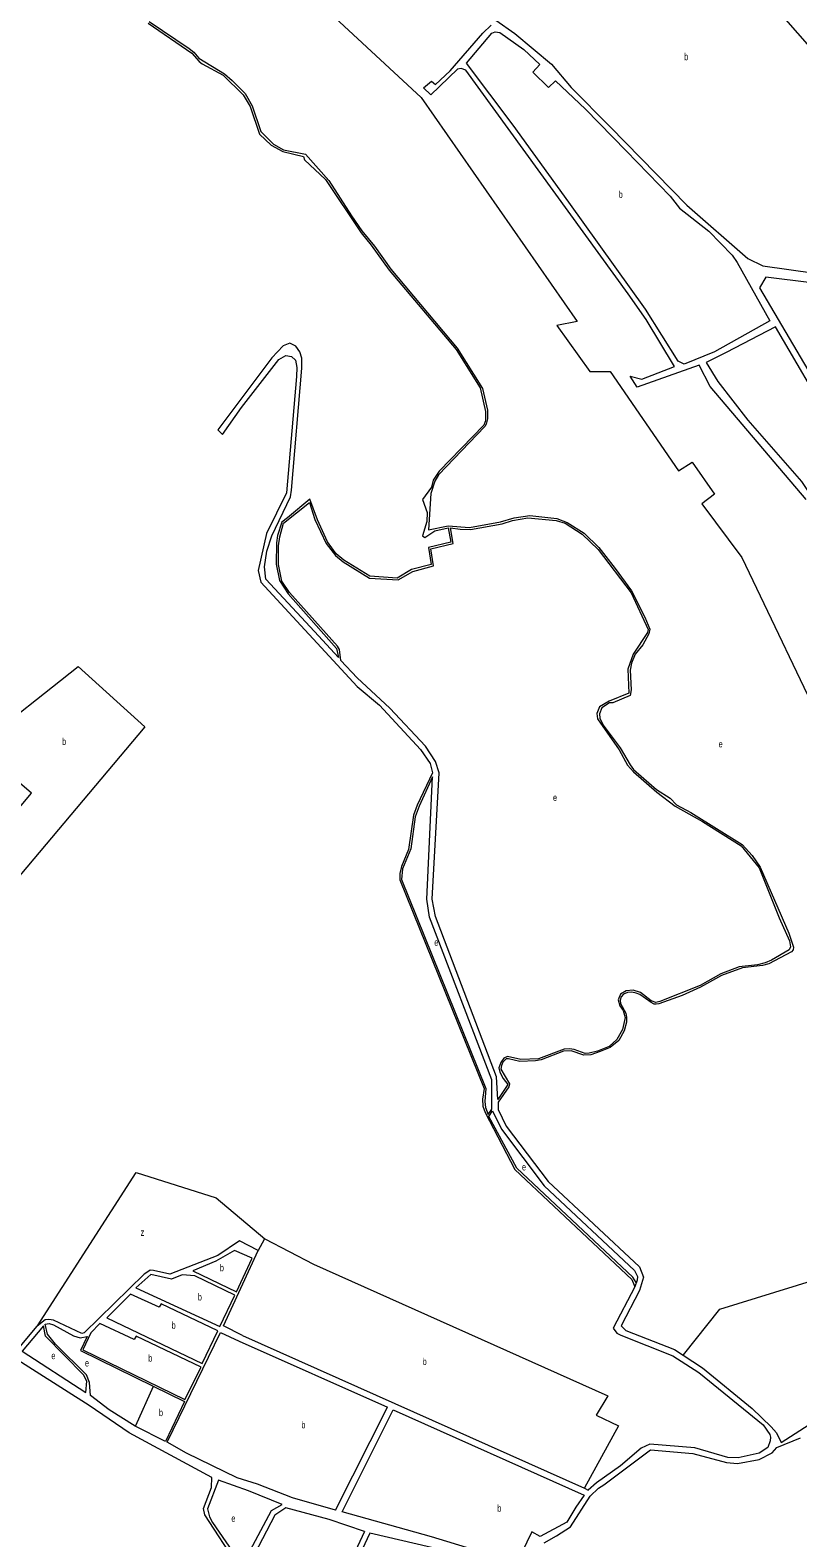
# Model space of a CAD drawing. Extents: x 639657 to 671642, y 222838 to 252123.
# Drawn here: x 646186 to 647287, y 244084 to 246247 of the extents above; entities that cross this region are included whole.
import ezdxf

# ---------------------------------------------------------------- set-up
doc = ezdxf.new("R2010")
doc.units = 0
doc.header["$LTSCALE"] = 4
doc.layers.add('1', color=7, linetype='Continuous', lineweight=13)
doc.layers.add('21', color=7, linetype='Continuous', lineweight=13)
doc.layers.add('7', color=7, linetype='Continuous')

msp = doc.modelspace()

# ---------------------------------------------------------------- linework, layer by layer
at = {"layer": '1'}
for p, q in [((647056.52, 244453.45), (647053.29, 244444.21)), ((646485.99, 244366.3), (646698.397, 244271.227)), ((646624.175, 244123.776), (646698.397, 244271.227)), ((646633.337, 244121.211), (646706.927, 244267.409)), ((646706.927, 244267.409), (646980.546, 244144.938)), ((646665.762, 244092.884), (646601.79, 243957.656)), ((646673.246, 244090.439), (646610.085, 243956.922))]:
    msp.add_line(p, q, dxfattribs=at)
for points in [[(647349.01, 246172.29), (647246.15, 246289.66)], [(646355.16, 246257.03), (646418.04, 246214.05), (646428.18, 246202.06), (646432.49, 246198.85), (646463.06, 246182.62), (646491.66, 246154.41), (646501.76, 246137.45), (646514.88, 246097.98), (646531.69, 246082.14), (646548.48, 246072.96), (646578.16, 246065.95), (646579.47, 246061.02), (646609.85, 246032.77), (646660.98, 245956.03), (646675.36, 245938.4), (646700.88, 245902.51), (646797.22, 245788.77), (646831.53, 245733.96), (646839, 245700.02), (646838.98, 245686.71), (646836.61, 245680.48), (646772.49, 245614.42), (646764.1, 245601.33), (646761.72, 245591.24), (646748.59, 245573.43), (646755.66, 245554.95), (646755.21, 245542.06), (646748.95, 245521.66), (646751.96, 245519.29), (646766.37, 245528.51), (646785.71, 245532.99), (646789.34, 245512.58), (646757.53, 245504.89), (646761.15, 245480.61), (646733.2, 245473.35), (646712.35, 245460.92), (646673.24, 245463.55), (646635.88, 245486.38), (646625.15, 245495.85), (646612.5, 245513.05), (646598.14, 245544.44), (646587.22, 245574.32), (646555.17, 245547.3), (646546.78, 245541.29), (646540.74, 245521.75), (646539.23, 245511.66), (646538.76, 245480.94), (646543.45, 245457.3), (646555.89, 245438.37), (646625.41, 245359.63), (646628.09, 245347.16), (646593.85, 245384.38)], [(646356.66, 246259.4), (646414.16, 246220.91), (646420.83, 246215.35), (646427.74, 246206.99), (646464.55, 246184.55), (646475.76, 246174.71), (646494.3, 246156.3), (646504.67, 246138.3), (646516.81, 246101.63), (646534.91, 246083.44), (646549.34, 246075.32), (646580.95, 246068.96), (646614.37, 246031.28), (646646.86, 245980.85), (646661.85, 245959.24), (646679.87, 245937.32), (646703.25, 245904), (646798.51, 245790.71), (646834.75, 245733.1), (646841.8, 245701.95), (646842.21, 245689.49), (646840.27, 245681.55), (646838.33, 245678.33), (646771.84, 245608.84), (646766.46, 245600.04), (646760.63, 245582.22), (646757.56, 245530.24), (646785.71, 245535.79), (646816.01, 245533.59), (646860.5, 245541.69), (646880.49, 245547.46), (646902.84, 245550.65), (646941.29, 245546.3), (646956.11, 245540.7), (646980.59, 245525.41), (647001.62, 245504.97), (647025.21, 245474.86), (647048.81, 245442.61), (647067.88, 245404.98), (647074.73, 245387.78), (647073.43, 245380.91), (647064.6, 245365.24), (647053.84, 245351.71), (647048.67, 245338.83), (647046.72, 245328.95), (647048.19, 245300.58), (647046.67, 245292.42), (647021.73, 245281.71), (647017.01, 245282.14), (647005.82, 245274.64), (647002.59, 245266.26), (647003.01, 245259.81), (647007.72, 245249.71), (647032.39, 245217.22), (647046.54, 245192.92), (647051.68, 245186.03), (647084.3, 245157.62), (647104.05, 245145.13), (647113.28, 245135.66), (647133.46, 245124.45), (647207.53, 245078.57), (647221.47, 245062.65), (647233.05, 245046.08), (647274.17, 244951.65), (647280.81, 244931.22), (647280.59, 244927.56), (647278, 244924.77)], [(647299.09, 245573.73), (647161.57, 245735.85), (647145.71, 245766.37), (647056.71, 245734.93), (647046.85, 245750.4), (647063.17, 245746.51), (647110.04, 245764.27), (647069.73, 245831.96), (647043.78, 245868.72), (646810.79, 246189.49), (646804.34, 246191.83), (646799.18, 246190.96), (646760.81, 246154.17), (646750.25, 246164.23), (646761.62, 246173.7), (646767.22, 246168.99), (646788.23, 246188.58), (646835.35, 246242.77), (646847.35, 246254.39)], [(646854.21, 246261.49), (646881.35, 246242.45), (646933.92, 246198.15), (646961.95, 246164.74), (647017.78, 246108.44), (647127.97, 245995.88), (647215.53, 245919.35), (647237, 245908.8), (647311.34, 245898.39)], [(646593.85, 245384.38), (646523.9, 245459.26), (646521.99, 245476.88), (646525.24, 245499.65), (646532.79, 245521.34), (646559.29, 245577.58), (646560.81, 245586.81), (646575.65, 245762.27), (646575.88, 245776.65), (646572.67, 245785.46), (646566.88, 245793.63), (646558.29, 245797.94), (646548.83, 245794.3), (646532.69, 245776.72), (646455.4, 245673.73), (646461.792, 245666.775), (646489.1, 245705.77), (646542.48, 245774.4), (646552.81, 245780.39), (646560.75, 245778.88), (646566.76, 245773.71), (646568.47, 245763.19), (646568.02, 245750.09), (646553.82, 245583.01), (646524.94, 245524.63), (646512.84, 245471.8), (646516.68, 245455.04), (646655.27, 245305.48), (646687.25, 245278.78), (646746.03, 245215.07), (646759.97, 245194.63), (646763.04, 245181.45), (646741.2, 245134.91), (646735.8, 245120.52), (646728.65, 245071.31), (646718.51, 245047.26), (646716.14, 245036.94), (646716.13, 245028.13), (646837.32, 244728.44), (646834.94, 244713.39), (646835.35, 244703.28), (646838.56, 244694.03), (646881.21, 244612.45), (647049, 244454.32), (647052.441, 244446.21), (647053.29, 244444.21)], [(646655, 245317.9), (646631.4, 245342.64), (646629.92, 245358.33), (646626.7, 245363.06), (646557.83, 245440.09), (646547.11, 245456.43), (646541.98, 245480.5), (646542.01, 245507.36), (646543.96, 245520.03), (646549.15, 245539.57), (646586.57, 245569.16), (646594.49, 245545.09), (646610.78, 245510.69), (646624.08, 245493.06), (646634.81, 245484.02), (646672.81, 245460.76), (646714.06, 245458.55), (646735.13, 245470.12), (646764.37, 245478.24), (646760.75, 245502.95), (646792.77, 245510.43), (646788.93, 245533.2), (646802.9, 245531.25), (646817.72, 245530.8), (646862.86, 245538.9), (646877.69, 245543.6), (646900.04, 245547.22), (646940.43, 245543.51), (646953.32, 245539.84), (646978.01, 245523.91), (647000.75, 245501.75), (647047.94, 245439.81), (647072.37, 245387.36), (647071.5, 245382.84), (647051.05, 245351.72), (647043.5, 245330.03), (647044.53, 245295.64), (647016.58, 245284.51), (647002.6, 245276.15), (646998.94, 245266.48), (646999.79, 245258.96), (647030.88, 245214.43), (647042.88, 245192.49), (647051.25, 245182.81), (647084.73, 245153.96), (647111.13, 245133.51), (647150.42, 245111.53), (647205.81, 245076.64), (647231.54, 245045.01), (647260.24, 244973.6), (647275.23, 244940.47), (647276.51, 244931.65), (647274.57, 244927.36), (647249.2, 244912.77), (647240.17, 244908.91), (647229.2, 244906.13), (647203.2, 244902.94), (647176.55, 244893.3), (647147.3, 244876.56), (647089.26, 244853.41), (647083.67, 244852.13), (647076.8, 244854.29), (647061.56, 244866.35), (647050.82, 244869.59), (647040.72, 244868.74), (647032.77, 244863.81), (647029.53, 244855.86), (647031.67, 244847.04), (647036.39, 244840.58), (647039.6, 244830.26), (647035.49, 244813.06), (647027.52, 244799.09), (647016.33, 244789), (646999.78, 244782.35), (646987.96, 244779.14), (646981.94, 244778.72), (646966.27, 244784.76), (646959.82, 244785.63), (646951.87, 244784.78), (646915.11, 244771.28), (646889.76, 244770.02), (646870.64, 244774.35), (646865.48, 244771.99), (646860.96, 244765.98), (646858.16, 244758.45), (646859.87, 244752), (646864.58, 244742.74), (646871.02, 244734.35), (646856.66, 244712.96), (646854.92, 244745.55), (646767.35, 244975.54), (646762.66, 245000.06), (646772.78, 245181.26), (646767.22, 245197.6), (646752.85, 245219.76)], [(646752.85, 245219.76), (646701.79, 245274.21), (646655, 245317.9)], [(647278, 244924.77), (647245.75, 244907.61), (647236.51, 244904.83)], [(647177.62, 244890.5), (647147.51, 244873.77), (647121.29, 244862.19), (647087.97, 244850.19), (647083.88, 244849.34), (647081.09, 244849.77), (647076.8, 244852.14), (647060.48, 244863.56), (647055.11, 244865.5), (647049.1, 244866.8), (647042.87, 244866.38), (647037.28, 244863.8), (647033.62, 244859.94), (647032.32, 244855.21), (647032.75, 244850.69), (647040.68, 244836.71), (647041.53, 244831.11), (647041.52, 244823.8), (647037.85, 244811.12), (647030.31, 244797.37), (647017.84, 244787.49), (647003.86, 244781.49), (646990.32, 244776.77), (646980.22, 244776.36), (646961.97, 244782.83), (646951.01, 244781.99), (646918.98, 244769.55), (646911.03, 244768.06), (646888.25, 244767.23), (646872.36, 244771.34), (646868.7, 244770.91), (646864.18, 244766.4), (646862.24, 244761.67), (646861.38, 244756.51), (646873.38, 244735.2), (646872.52, 244731.12), (646857.45, 244708.77), (646857.43, 244698.45), (646869, 244674.77), (646928.84, 244595.32), (647060.15, 244472.53), (647065.94, 244457.89), (647060.11, 244438.96), (647033.82, 244388.21), (647040.48, 244381.32), (647110.48, 244353.9), (647122.806, 244345.847)], [(647236.51, 244904.83), (647207.71, 244901.64), (647177.62, 244890.5)], [(646513.01, 244495.99), (646486.18, 244510.01), (646455, 244489.19), (646386.21, 244462.19), (646363.01, 244467.38), (646358.28, 244467.82), (646354.63, 244465.67), (646349.47, 244462.24), (646263.63, 244377.81), (646259.98, 244376.95), (646219.4, 244396.16), (646212.95, 244397.03), (646207.37, 244396.61), (646196.115, 244387.661)], [(646490.51, 244374.25), (646463.24, 244387.85), (646513.01, 244495.99)], [(647053.29, 244444.21), (647022.48, 244384.66), (647027.63, 244377.77), (647033.21, 244374.53), (647107.72, 244344.95), (647145.29, 244321.23), (647237.56, 244245.79), (647247, 244232.22), (647247.85, 244228.13), (647247.42, 244222.97), (647244.18, 244213.29), (647231.49, 244205.35), (647201.41, 244198.5), (647186.59, 244199.39), (647139.55, 244213.01), (647075.11, 244218.27), (647062.64, 244212.69), (647032.74, 244187.13), (646998.55, 244162.86), (646986.443, 244152.495)], [(646196.115, 244387.661), (646195.75, 244387.37), (646168.85, 244355.57), (646150.85, 244366.208)], [(646210.92, 244376.18), (646207.71, 244390.6), (646213.3, 244391.46), (646219.31, 244389.51), (646248.08, 244373.76), (646257.75, 244370.95), (646267.63, 244372.88), (646258.15, 244352.45), (646362.444, 244301.398)], [(646336.65, 244243.89), (646299.51, 244267.61), (646272.68, 244288.09), (646271.2, 244306.81), (646266.7, 244317.58), (646222.5, 244361.75), (646210.92, 244376.18)], [(646624.175, 244123.776), (646562.32, 244141.09), (646512.15, 244160.96), (646482.94, 244169.83), (646410.37, 244205.23), (646382.67, 244220.98), (646458.93, 244378.6), (646485.99, 244366.3)], [(646490.51, 244374.25), (646980.937, 244154.957), (646986.443, 244152.495)], [(646484.06, 244044.13), (646436.46, 244116.73), (646434.54, 244126.2), (646446.18, 244155.89), (646446.63, 244170.31), (646327.9, 244234.61), (646270.8, 244273.65), (646154.02, 244347.84)], [(647122.806, 244345.847), (647150.4, 244327.82), (647221.65, 244269.41), (647249.11, 244243.34), (647256.62, 244234.5), (647263.04, 244220.72), (647341.97, 244271.2), (647409.25, 244297.6), (647462.33, 244306.36), (647592.78, 244332.25), (647604.902, 244336.683)], [(646362.444, 244301.398), (646407.16, 244279.51), (646380.23, 244222.09), (646336.65, 244243.89)], [(646923.38, 244076.91), (646941.23, 244086.57), (646961.23, 244099.68), (646989.43, 244143.78), (647001.05, 244154.95), (647009.01, 244160.11), (647076.01, 244210.21), (647136.69, 244204.94), (647185.01, 244191.97), (647200.7, 244190.45), (647231.86, 244196.44), (647250.35, 244205.88), (647257.02, 244213.62), (647290.77, 244227.14)], [(646980.546, 244144.938), (646968.64, 244128.04), (646955.72, 244106.32), (646917.67, 244085.93), (646905.65, 244092.4), (646884.11, 244047.88), (646761.7, 244085.28), (646633.337, 244121.211)], [(646665.762, 244092.884), (646614.91, 244110.07), (646552.87, 244127.14), (646536.91, 244116.41), (646496.02, 244037.64), (646561.117, 243966.133)], [(646919.543, 244021.867), (646900.74, 244026.39), (646761.59, 244070.06), (646673.246, 244090.439)]]:
    msp.add_lwpolyline(points, dxfattribs=at)
for points in [[(646958.64, 246000.44), (646878.93, 246110.89), (646811.83, 246199.79), (646848.46, 246242.8), (646852.97, 246244.75), (646859.85, 246243.9), (646894.31, 246219.3), (646917.15, 246197.68), (646907.08, 246186.93), (646929.29, 246164.66), (646939.57, 246174.13), (646982.46, 246133.67), (647041.09, 246073.73), (647104.23, 246008.75), (647117.21, 245991.84), (647159.5, 245958.5), (647192.97, 245924.11), (647200.27, 245913.79), (647247.21, 245829.78), (647167.65, 245785.45), (647124.01, 245767.9), (647115.64, 245771.99), (647068.89, 245846.78)], [(647306.59, 245884.44), (647241.06, 245892.48), (647232.23, 245877.25), (647343.93, 245687.28), (647351.44, 245676.96), (647387.06, 245644.05), (647484.09, 245734.98), (647452.58, 245792.99), (647377.02, 245852.36), (647351.69, 245868.28), (647320.98, 245880.77)], [(647336.83, 245681.71), (647254.94, 245821.39), (647184.41, 245784.35), (647155.6, 245770.22), (647172.32, 245743.14), (647215.44, 245687.46), (647292.24, 245599.3), (647421.97, 245403.21), (647466.48, 245427.65), (647502.39, 245445.22), (647494.05, 245473.15), (647415.8, 245601.71), (647393.48, 245625.58)], [(646842.86, 244691.23), (646848.02, 244698.96), (646848.08, 244740.89), (646758.81, 244974.53), (646754.98, 245000.12), (646762.93, 245175.54), (646743.99, 245133.84), (646738.38, 245118.15), (646731.87, 245072.6), (646720.23, 245043.81), (646718.49, 245028.55), (646839.69, 244728.43), (646838.16, 244710.16), (646839, 244701.34)], [(647056.52, 244453.45), (647055.31, 244450), (647050.3, 244457.98), (646884, 244614.39), (646844.14, 244688.43), (646849.24, 244696.48), (646862.17, 244670.12), (646923.29, 244588.73), (647053.1, 244467.22), (647056.96, 244458.61)], [(646504.32, 244485.06), (646478.98, 244496.07), (646452.53, 244480.83), (646419.43, 244466.89), (646482.13, 244436.69)], [(646458, 244387.02), (646479.76, 244431.96), (646422.21, 244459.58), (646404.17, 244461.32), (646388.91, 244454.89), (646359.05, 244461.82), (646337.76, 244442.49)], [(646432.8, 244333.91), (646455.2, 244380.79), (646374.04, 244419.63), (646371.02, 244414.9), (646329.8, 244433.68), (646295.81, 244399.73)], [(646205.04, 244388.09), (646174.72, 244351.76), (646266.05, 244292.4), (646267.49, 244308.61), (646262.44, 244317.75), (646208.09, 244373.27)], [(646408.02, 244282.31), (646431.29, 244328.97), (646338.1, 244373.21), (646335.3, 244368.48), (646286.13, 244391.35), (646272.8, 244377.82), (646261.59, 244353.73)], [(646532.34, 244123.28), (646547.56, 244131.62), (646499.38, 244151.12), (646456.22, 244166.68), (646440.27, 244125.59), (646443.26, 244114.18), (646447.76, 244105.78), (646490.14, 244044.35)]]:
    msp.add_lwpolyline(points, close=True, dxfattribs=at)
at = {"layer": '21'}
for points in [[(646616.909, 246270.82), (646746.923, 246150.535), (646970.602, 245828.842), (646941.244, 245823.247), (646988.776, 245757.51), (647018.134, 245757.51), (647115.994, 245614.846), (647135.566, 245627.434), (647167.72, 245581.278), (647149.546, 245567.292), (647206.864, 245490.365), (647332.683, 245227.416), (647392.797, 245094.543), (647508.831, 244856.77), (647527.005, 244863.763), (647538.189, 244834.392), (647554.965, 244835.79), (647578.731, 244732.289), (647626.263, 244700.12), (647624.865, 244609.207), (647700.357, 244448.36), (647726.09, 244453.775), (647726.59, 244453.88)], [(646196.115, 244387.661), (646196.437, 244388.16), (646338.01, 244608.157), (646452.646, 244571.792), (646522.546, 244513.048)], [(646513.01, 244495.99), (646513.29, 244496.49), (646522.266, 244512.548), (646522.546, 244513.048)], [(646522.546, 244513.048), (646592.446, 244476.682), (647014.641, 244287.863), (646997.866, 244259.89), (647030.019, 244244.504), (646981.211, 244155.457), (646980.937, 244154.957)], [(647122.806, 244345.847), (647123.204, 244346.347), (647175.402, 244411.999), (647365.53, 244470.743), (647392.092, 244452.56), (647470.38, 244448.364), (647607.384, 244463.749), (647636.741, 244470.743), (647645.129, 244439.972), (647593.404, 244372.836), (647604.902, 244336.683)], [(646362.444, 244301.398), (646362.22, 244300.898), (646336.874, 244244.39), (646336.65, 244243.89)]]:
    msp.add_lwpolyline(points, dxfattribs=at)
msp.add_lwpolyline([(646350.534, 245247.58), (646145.785, 245003.979), (646011.578, 245124.264), (646047.926, 245160.63), (646129.009, 245082.304), (646187.725, 245152.238), (646109.437, 245219.374), (646254.829, 245334.064)], close=True, dxfattribs=at)

# ---------------------------------------------------------------- texts
at = {"layer": '7'}
for s, width, p in [('b', 0.75, (647124.14, 246203.96)), ('b', 0.75, (647030.242, 246006.325)), ('b', 0.75, (646231.806, 245221.404)), ('e', 0.75, (647173.619, 245217.986)), ('e', 0.75, (646935.959, 245141.06)), ('e', 0.75, (646765.726, 244933.385)), ('e', 0.75, (646891.546, 244610.993)), ('z', 0.8, (646344.345, 244517.176)), ('b', 0.75, (646458.12, 244466.38)), ('b', 0.75, (646426.519, 244424.42)), ('b', 0.75, (646388.948, 244383.795)), ('e', 0.75, (646216.428, 244340.245)), ('e', 0.75, (646264.659, 244329.755)), ('b', 0.75, (646355.486, 244336.83)), ('b', 0.75, (646749.065, 244331.853)), ('b', 0.75, (646370.746, 244258.521)), ('b', 0.75, (646575.014, 244240.939)), ('e', 0.75, (646474.651, 244106.809)), ('b', 0.75, (646856.012, 244121.354))]:
    msp.add_text(s, height=10, dxfattribs=dict(at, width=width)).set_placement(p)

doc.saveas('drawing.dxf')
